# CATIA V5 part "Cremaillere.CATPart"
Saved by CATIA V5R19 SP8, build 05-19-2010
Part number: Cremaillere
Bounding box of the stored display mesh (mm): x -165 to 165, y -800 to 700, z -1690 to -1650
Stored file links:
  G:\EU_thinkMotion\CFAO_2010\MMS_groupe3\MMS_groupe3\rdalborgo\rdalborgo\Cremaillere.CATPart
  G:\EU_thinkMotion\CFAO_2010\MMS_groupe3\MMS_groupe3\rdalborgo\rdalborgo\rdalborgo.CATProduct
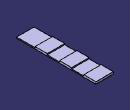
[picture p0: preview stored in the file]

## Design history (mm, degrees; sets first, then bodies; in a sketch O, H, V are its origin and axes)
External parameters (linked from other documents)
  `External.X Cremaillere` = 330 mm
  `External.Y Cremaillere` = 230 mm
Set1
  Plane1: linked copy from another document
  Point1 "Origine": linked copy from another document
Body1 (main body)
  Sketch1 on Plane1, origin (0, 0, -1670), H (1, 0, 0), V (0, 1, 0)
    line L1 (-165, 700) -> (165, 700)
    line L2 (165, 700) -> (165, -800)
    line L3 (165, -800) -> (-165, -800)
    line L4 (-165, -800) -> (-165, 700)
    reference projected point E1 (0, 0) from Point1
    reference projected point E2 (0, 0) from Point1
    distance L4 L2 = 330 {= `External.X Cremaillere`}
    distance L1 L3 = 1500
    distance L2 E1 = 165 {= `External.X Cremaillere` /2}
    distance L3 E2 = 800
    horizontal: L1 H, L3 H
    vertical: L2 V, L4 V
  Pad1: profile Sketch1, direction (0, 0, -1), length 20
  Sketch2 on Plane1, origin (0, 0, -1670), H (1, 0, 0), V (0, 1, 0)
    line L1 (-165, 700) -> (165, 700)
    line L2 (165, 700) -> (165, 470)
    line L3 (165, 470) -> (-165, 470)
    line L4 (-165, 470) -> (-165, 700)
    reference projected point E1 (0, 0) from Point1
    reference projected point E2 (0, 0) from Point1
    distance L4 L2 = 330 {= `External.X Cremaillere`}
    distance L3 L1 = 230 {= `External.Y Cremaillere`}
    distance L2 E1 = 165 {= `External.X Cremaillere` /2}
    distance L1 E2 = 700
    horizontal: L1 H, L3 H
    vertical: L2 V, L4 V
  Pad2: profile Sketch2, direction (0, 0, 1), length 20
  RectPattern1: of Pad2, direction 1 instances 1, spacing 20, along Plane1, direction 2 instances 3, spacing 460 {= `External.Y Cremaillere` *2}, along Plane1 reversed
